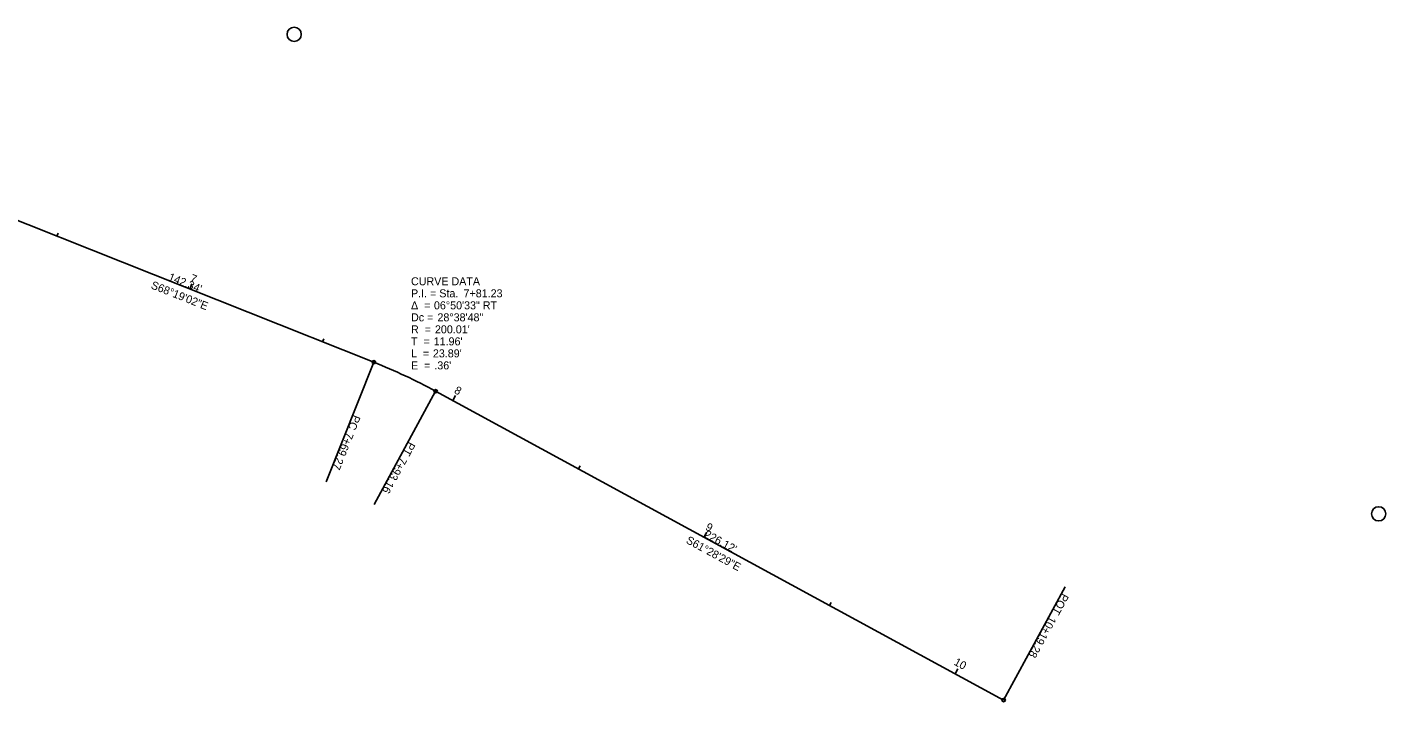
# Model space of a CAD drawing. Extents: x 2001143 to 2002244, y 252727 to 252963.
# Drawn here: x 2001769 to 2002244.2, y 252727.4 to 252963.3 of the extents above; entities that cross this region are included whole.
import ezdxf

# ---------------------------------------------------------------- set-up
doc = ezdxf.new("R2010")
doc.units = 0
for name, color, linetype in [('DT_P_Break_Line', 7, 'Continuous'), ('DT_P_Contour_Major', 7, 'Continuous'), ('DT_P_Contour_Minor', 7, 'Continuous'), ('DT_P_Spot_Elevations', 7, 'Continuous'), ('DT_P_TIN_Hull', 7, 'Continuous'), ('DT_P_Void', 7, 'Continuous'), ('DT_X_Contour_Minor', 7, 'Continuous'), ('DT_X_Spot_Elev', 7, 'Continuous')]:
    doc.layers.add(name, color=color, linetype=linetype)

msp = doc.modelspace()

# ---------------------------------------------------------------- linework, layer by layer
at = {"layer": 'DT_P_Break_Line'}
for p, q in [((2001825.84, 252871.74), (2001826.28, 252872.86)), ((2001890.21, 252846.15), (2001873.59, 252804.33)), ((2001911.83, 252836.02), (2001890.34, 252796.48)), ((2001917.84, 252832.75), (2001918.41, 252833.81)), ((2002005.7, 252785), (2002006.27, 252786.05)), ((2002110.5, 252728.04), (2002131.99, 252767.58)), ((2002093.56, 252737.24), (2002094.51, 252739))]:
    msp.add_line(p, q, dxfattribs=at)
for centre in [(2001890.21, 252846.15), (2001911.83, 252836.02), (2002110.5, 252728.04)]:
    msp.add_circle(centre, 0.6, dxfattribs=at)
at = {"layer": 'DT_P_Contour_Minor'}
for p, q in [((2001757.95, 252898.74), (2001890.21, 252846.15)), ((2001911.83, 252836.02), (2002110.5, 252728.04))]:
    msp.add_line(p, q, dxfattribs=at)
msp.add_arc((2001816.31, 252660.29), 200.01, 61.4747, 68.3173, dxfattribs=at)
msp.add_arc((2001816.31, 252660.29), 200.01, 61.4747, 68.3173, dxfattribs=at)
at = {"layer": 'DT_P_Spot_Elevations'}
for p, q in [((2001779.38, 252890.21), (2001779.82, 252891.33)), ((2001825.84, 252871.74), (2001826.58, 252873.6)), ((2001872.3, 252853.27), (2001872.75, 252854.38)), ((2001890.21, 252846.15), (2001873.59, 252804.33)), ((2001911.83, 252836.02), (2001890.34, 252796.48)), ((2001917.84, 252832.75), (2001918.79, 252834.51)), ((2001961.77, 252808.88), (2001962.34, 252809.93)), ((2002005.7, 252785), (2002006.65, 252786.76)), ((2002110.5, 252728.04), (2002131.99, 252767.58)), ((2002049.63, 252761.12), (2002050.2, 252762.18)), ((2002093.56, 252737.24), (2002094.51, 252739))]:
    msp.add_line(p, q, dxfattribs=at)
for centre in [(2001890.21, 252846.15), (2001911.83, 252836.02), (2002110.5, 252728.04)]:
    msp.add_circle(centre, 0.6, dxfattribs=at)
at = {"layer": 'DT_P_TIN_Hull'}
for centre in [(2001862.35, 252960.8), (2002241.68, 252793.16)]:
    msp.add_circle(centre, 2.5, dxfattribs=at)
at = {"layer": 'DT_X_Contour_Minor'}
for p, q in [((2001890.21, 252846.15), (2001873.59, 252804.33)), ((2001911.83, 252836.02), (2001890.34, 252796.48)), ((2002110.5, 252728.04), (2002131.99, 252767.58)), ((2002093.56, 252737.24), (2002094.51, 252739))]:
    msp.add_line(p, q, dxfattribs=at)
for centre in [(2001890.21, 252846.15), (2001911.83, 252836.02), (2002110.5, 252728.04)]:
    msp.add_circle(centre, 0.6, dxfattribs=at)

# ---------------------------------------------------------------- texts
at = {"layer": 'DT_P_Break_Line'}
for s, rotation, p in [('PC', 248.3173, (2001883.04, 252827.97)), ('7+69.27', 248.3173, (2001880.63, 252821.91)), ('PT', 241.4747, (2001902.41, 252818.59)), ('7+93.16', 241.4747, (2001899.5, 252813.24)), ('POT', 241.4747, (2002130.97, 252765.61)), ('10+19.28', 241.4747, (2002126.61, 252757.59)), ('10', 331.4747, (2002092.85, 252740.53))]:
    msp.add_text(s, height=2.8, rotation=rotation, dxfattribs=at).set_placement(p)
at = {"layer": 'DT_P_Contour_Major'}
for s, rotation, p in [("142.34'", 338.3173, (2001818.07, 252874.88)), ('S68°19\'02"E', 338.3173, (2001812.02, 252872.07)), ("226.12'", 331.4747, (2002005.49, 252785.17)), ('S61°28\'29"E', 331.4747, (2001999.14, 252783.1))]:
    msp.add_text(s, height=2.8, rotation=rotation, dxfattribs=at).set_placement(p)
for s, p in [('CURVE DATA', (2001903.22, 252873.06)), ('Δ  = ', (2001903.22, 252864.66)), ('P.I. = Sta. ', (2001903.22, 252868.86)), ('06°50\'33" RT', (2001911.24, 252864.66)), ('7+81.23', (2001921.59, 252868.86)), ('Dc = ', (2001903.22, 252860.46)), ('28°38\'48"', (2001912.46, 252860.46)), ('R  = ', (2001903.22, 252856.26)), ("200.01'", (2001911.59, 252856.26)), ('T  = ', (2001903.22, 252852.06)), ("11.96'", (2001911.15, 252852.06)), ('L  = ', (2001903.22, 252847.86)), ("23.89'", (2001910.87, 252847.86)), ('E  = ', (2001903.22, 252843.66)), (".36'", (2001911.37, 252843.66))]:
    msp.add_text(s, height=2.8, dxfattribs=at).set_placement(p)
at = {"layer": 'DT_P_Spot_Elevations'}
for s, rotation, p in [('7', 338.3173, (2001825.68, 252874.49)), ('8', 331.4747, (2001918.09, 252835.52)), ('PC', 248.3173, (2001883.04, 252827.97)), ('7+69.27', 248.3173, (2001880.63, 252821.91)), ('PT', 241.4747, (2001902.41, 252818.59)), ('7+93.16', 241.4747, (2001899.5, 252813.24)), ('9', 331.4747, (2002005.97, 252787.75)), ('POT', 241.4747, (2002130.97, 252765.61)), ('10+19.28', 241.4747, (2002126.61, 252757.59)), ('10', 331.4747, (2002092.85, 252740.53))]:
    msp.add_text(s, height=2.8, rotation=rotation, dxfattribs=at).set_placement(p)
at = {"layer": 'DT_P_Void'}
for s, rotation, p in [("142.34'", 338.3173, (2001818.07, 252874.88)), ('S68°19\'02"E', 338.3173, (2001812.02, 252872.07)), ("226.12'", 331.4747, (2002005.49, 252785.17)), ('S61°28\'29"E', 331.4747, (2001999.14, 252783.1))]:
    msp.add_text(s, height=2.8, rotation=rotation, dxfattribs=at).set_placement(p)
for s, p in [('CURVE DATA', (2001903.22, 252873.06)), ('Δ  = ', (2001903.22, 252864.66)), ('P.I. = Sta. ', (2001903.22, 252868.86)), ('06°50\'33" RT', (2001911.24, 252864.66)), ('7+81.23', (2001921.59, 252868.86)), ('Dc = ', (2001903.22, 252860.46)), ('28°38\'48"', (2001912.46, 252860.46)), ('R  = ', (2001903.22, 252856.26)), ("200.01'", (2001911.59, 252856.26)), ('T  = ', (2001903.22, 252852.06)), ("11.96'", (2001911.15, 252852.06)), ('L  = ', (2001903.22, 252847.86)), ("23.89'", (2001910.87, 252847.86)), ('E  = ', (2001903.22, 252843.66)), (".36'", (2001911.37, 252843.66))]:
    msp.add_text(s, height=2.8, dxfattribs=at).set_placement(p)
at = {"layer": 'DT_X_Contour_Minor'}
for s, rotation, p in [('PC', 248.3173, (2001883.04, 252827.97)), ('7+69.27', 248.3173, (2001880.63, 252821.91)), ('PT', 241.4747, (2001902.41, 252818.59)), ('7+93.16', 241.4747, (2001899.5, 252813.24)), ('POT', 241.4747, (2002130.97, 252765.61)), ('10+19.28', 241.4747, (2002126.61, 252757.59)), ('10', 331.4747, (2002092.85, 252740.53))]:
    msp.add_text(s, height=2.8, rotation=rotation, dxfattribs=at).set_placement(p)
at = {"layer": 'DT_X_Spot_Elev'}
for s, rotation, p in [("142.34'", 338.3173, (2001818.07, 252874.88)), ('S68°19\'02"E', 338.3173, (2001812.02, 252872.07)), ("226.12'", 331.4747, (2002005.49, 252785.17)), ('S61°28\'29"E', 331.4747, (2001999.14, 252783.1))]:
    msp.add_text(s, height=2.8, rotation=rotation, dxfattribs=at).set_placement(p)
for s, p in [('CURVE DATA', (2001903.22, 252873.06)), ('Δ  = ', (2001903.22, 252864.66)), ('P.I. = Sta. ', (2001903.22, 252868.86)), ('06°50\'33" RT', (2001911.24, 252864.66)), ('7+81.23', (2001921.59, 252868.86)), ('Dc = ', (2001903.22, 252860.46)), ('28°38\'48"', (2001912.46, 252860.46)), ('R  = ', (2001903.22, 252856.26)), ("200.01'", (2001911.59, 252856.26)), ('T  = ', (2001903.22, 252852.06)), ("11.96'", (2001911.15, 252852.06)), ('L  = ', (2001903.22, 252847.86)), ("23.89'", (2001910.87, 252847.86)), ('E  = ', (2001903.22, 252843.66)), (".36'", (2001911.37, 252843.66))]:
    msp.add_text(s, height=2.8, dxfattribs=at).set_placement(p)

doc.saveas('drawing.dxf')
